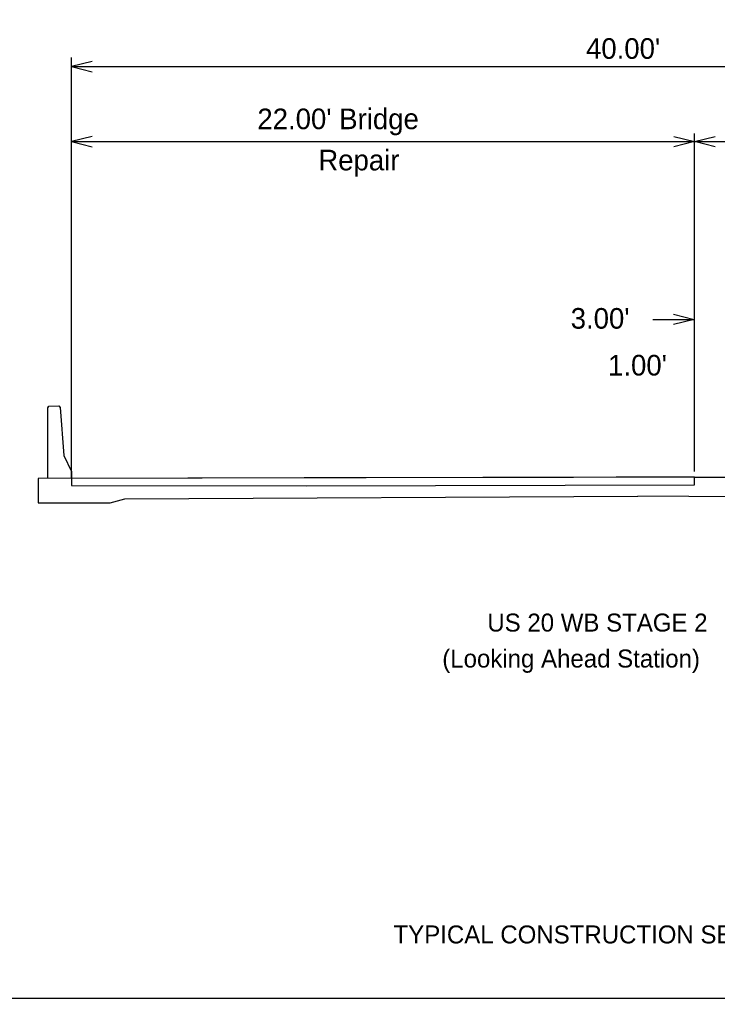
# Model space of a CAD drawing. Extents: x 8410 to 81668, y 7924 to 12712.
# Drawn here: x 14618 to 15388, y 7924 to 9002 of the extents above; entities that cross this region are included whole.
import ezdxf

# ---------------------------------------------------------------- set-up
doc = ezdxf.new("R2010")
doc.units = 0
for name, color, linetype in [('Level 2', 7, 'Continuous'), ('Level 3', 7, 'Continuous'), ('SheetBorder', 7, 'Continuous')]:
    doc.layers.add(name, color=color, linetype=linetype)

msp = doc.modelspace()

# ---------------------------------------------------------------- linework, layer by layer
at = {"layer": 'Level 2'}
for p, q in [((14675.7, 8496.8), (14675.7, 8960.7)), ((14675.7, 8950.7), (15924.3, 8950.7)), ((15362.5, 8504.6), (15362.5, 8876.9)), ((14675.7, 8868), (15362.5, 8868)), ((15362.5, 8868), (15924.3, 8868)), ((15316.6, 8672.1), (15362, 8672.1)), ((14649.4, 8574.8), (14650.7, 8576.7)), ((14649.4, 8496.7), (14649.4, 8574.8)), ((14650.7, 8576.7), (14661.6, 8576.9)), ((14661.6, 8576.9), (14663, 8575.1)), ((14663, 8575.1), (14667.1, 8522)), ((14667.1, 8522), (14675.6, 8504.7)), ((14675.6, 8504.7), (14675.7, 8496.8)), ((14734.5, 8474.4), (15300, 8477.3)), ((15865.5, 8474.4), (15300, 8477.3)), ((14718.3, 8469.9), (14734.5, 8474.4))]:
    msp.add_line(p, q, dxfattribs=at)
for points in [[(14698.4, 8956.3), (14675.7, 8950.7), (14698.4, 8945)], [(14698.4, 8873.6), (14675.7, 8868), (14698.4, 8862.3)], [(15339.7, 8873.6), (15362.5, 8868), (15339.7, 8862.3)], [(15385.2, 8862.3), (15362.5, 8868), (15385.2, 8873.6)], [(15339.3, 8677.8), (15362, 8672.1), (15339.3, 8666.4)], [(14638.8, 8496.7), (14638.8, 8469.9), (14718.3, 8469.9)]]:
    msp.add_lwpolyline(points, dxfattribs=at)
at = {"layer": 'Level 3'}
for p, q in [((15362.5, 8498.4), (14638.8, 8496.7)), ((15362.5, 8498.4), (15961.2, 8496.7)), ((14934.1, 8488.7), (15362.5, 8490)), ((15362.5, 8490), (15362.5, 8494.6))]:
    msp.add_line(p, q, dxfattribs=at)
for points in [[(15362.5, 8494.6), (15362.5, 8498.4), (15353.3, 8498.4), (15334.8, 8498.3), (15308.8, 8498.3), (15276.1, 8498.2), (15229, 8498.1), (15163.6, 8497.9), (15129.2, 8497.9), (14932, 8497.4)], [(14932, 8497.4), (14675.7, 8496.8), (14675.7, 8489.2), (14934.1, 8488.7)]]:
    msp.add_lwpolyline(points, dxfattribs=at)
at = {"layer": 'SheetBorder'}
msp.add_lwpolyline([(13732.5, 9944), (16867.5, 9944), (16867.5, 7924), (13732.5, 7924)], close=True, dxfattribs=at)

# ---------------------------------------------------------------- texts
at = {"layer": 'Level 2'}
for s, height, p in [("40.00'", 22.71, (15242.8, 8959.2)), ("22.00' Bridge", 22.709, (14880.5, 8881.7)), ('Repair', 22.71, (14947.7, 8836.3)), ("3.00'", 22.71, (15225.9, 8661.9)), ("1.00'", 22.71, (15267.1, 8610.3)), ('US 20 WB STAGE 2', 19.8, (15134, 8328.2)), ('(Looking Ahead Station)', 19.8, (15084.3, 8288.6)), ('TYPICAL CONSTRUCTION SECTIONS', 19.8, (15030.6, 7984.6))]:
    msp.add_text(s, height=height, dxfattribs=at).set_placement(p)

doc.saveas('drawing.dxf')
